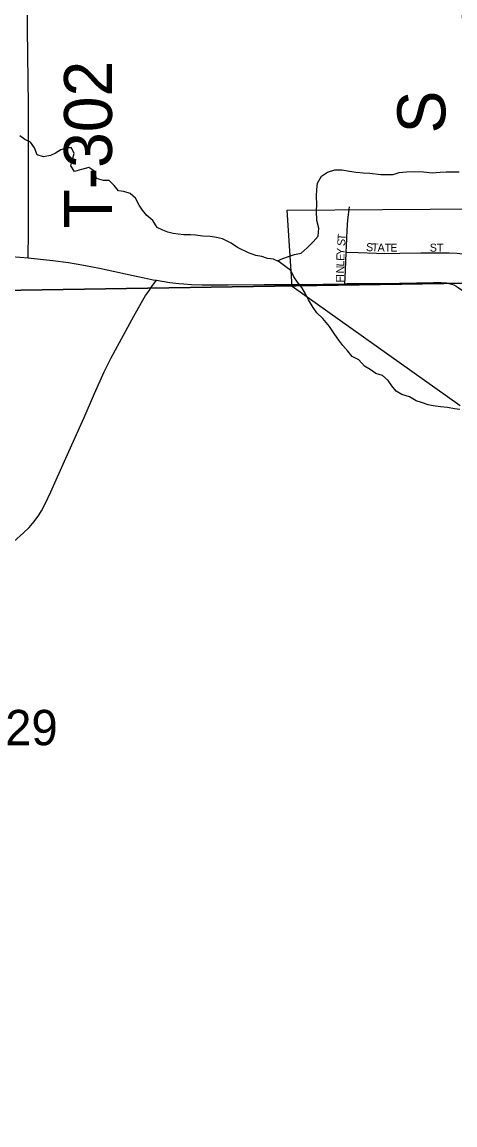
# Model space of a CAD drawing. Extents: x 1985906 to 2360102, y 891258 to 1222054.
# Drawn here: x 2147577 to 2150284, y 999101 to 1005993 of the extents above; entities that cross this region are included whole.
import ezdxf

# ---------------------------------------------------------------- set-up
doc = ezdxf.new("R2010")
doc.units = 0
for name, color, linetype in [('GM_X_City_Street', 7, 'Continuous'), ('GM_X_City_Street_Text', 7, 'Continuous'), ('GM_X_Corporation', 7, 'Continuous'), ('GM_X_County_Road_Text', 7, 'Continuous'), ('GM_X_Minor_River', 7, 'Continuous'), ('GM_X_Section', 7, 'Continuous'), ('GM_X_Section_Text', 7, 'Continuous'), ('GM_X_Township_Road', 7, 'Continuous'), ('GM_X_Township_Road_Text', 7, 'Continuous'), ('GM_X_US_Route', 7, 'Continuous')]:
    doc.layers.add(name, color=color, linetype=linetype)

msp = doc.modelspace()

# ---------------------------------------------------------------- linework, layer by layer
at = {"layer": 'GM_X_City_Street'}
for points in [[(2149604.5, 1004554.5), (2149606.6, 1004593.2), (2149609.8, 1004691.6), (2149614.7, 1004756.6), (2149623, 1004821.8), (2149624.4, 1004838.1)], [(2149594.7, 1004358), (2149596.5, 1004396.7), (2149601.3, 1004494.9), (2149604.5, 1004554.5)], [(2149604.5, 1004554.5), (2149608.6, 1004554.4), (2149679.7, 1004553.3), (2149793.5, 1004548.1), (2149842.2, 1004546.9), (2149939.6, 1004548.5), (2150069.7, 1004550.9), (2150248.8, 1004550.7), (2150297.5, 1004548.5), (2150313.7, 1004546.8), (2150345.6, 1004543.5)]]:
    msp.add_lwpolyline(points, dxfattribs=at)
at = {"layer": 'GM_X_Corporation'}
msp.add_lwpolyline([(2150317.2, 1003594.5), (2149265.4, 1004339.5), (2149235.5, 1004817.2), (2150726.1, 1004827.3)], dxfattribs=at)
at = {"layer": 'GM_X_Minor_River'}
for points in [[(2148086.7, 1005002.3), (2148042.5, 1005016), (2148032.1, 1005058.1), (2147993.7, 1005083.9), (2147947.6, 1005071.5), (2147905.6, 1005059.1), (2147881.2, 1005095), (2147890.9, 1005127.2), (2147902.6, 1005171.5), (2147886.2, 1005207.5), (2147854.1, 1005207.2), (2147820.1, 1005194.9), (2147786.1, 1005174.5), (2147754.2, 1005158.2), (2147710.1, 1005149.8), (2147671.8, 1005163.6), (2147655.4, 1005207.6), (2147629, 1005241.5), (2147594.7, 1005259.3), (2147562.4, 1005281.1)], [(2149174.3, 1004500), (2149207.1, 1004515.6), (2149243.1, 1004527.9), (2149281.2, 1004540.3), (2149323.2, 1004548.7), (2149359.1, 1004581.1), (2149396.9, 1004619.5), (2149428.7, 1004655.9), (2149432.3, 1004704.2), (2149419.9, 1004752.2), (2149417.4, 1004812.4), (2149421, 1004852.6), (2149418.6, 1004904.8), (2149420.2, 1004947), (2149423.9, 1004985.2), (2149449.6, 1005029.5), (2149487.6, 1005055.9), (2149533.6, 1005070.4), (2149575.8, 1005068.7), (2149624, 1005061.1), (2149666.3, 1005055.4), (2149710.5, 1005049.8), (2149752.6, 1005048.1), (2149821, 1005040.6), (2149897.2, 1005041.2), (2149935.3, 1005053.6), (2149981.4, 1005058), (2150029.6, 1005058.4), (2150087.8, 1005056.8), (2150142.1, 1005051.3), (2150192.2, 1005055.7), (2150228.3, 1005058), (2150266.5, 1005056.3), (2150310.7, 1005056.7)], [(2150315.3, 1003571), (2150281.1, 1003576.7), (2150236.8, 1003584.4), (2150192.6, 1003588), (2150148.4, 1003595.7), (2150116.2, 1003601.5), (2150074, 1003615.2), (2150041.8, 1003626.9), (2149999.4, 1003650.7), (2149951.1, 1003666.4), (2149916.8, 1003686.2), (2149888.4, 1003720.1), (2149866, 1003754), (2149831.6, 1003783.8), (2149789.4, 1003797.5), (2149753, 1003821.3), (2149718.7, 1003843.2), (2149682.2, 1003883), (2149641.9, 1003902.8), (2149613.5, 1003936.7), (2149583.1, 1003972.5), (2149558.7, 1004004.5), (2149532.3, 1004040.4), (2149499.8, 1004090.3), (2149457.2, 1004140.2), (2149420.8, 1004176), (2149396.4, 1004209.9), (2149367.9, 1004257.9), (2149349.5, 1004293.9), (2149327.1, 1004333.8), (2149298.7, 1004367.8), (2149276.3, 1004401.7), (2149257.9, 1004439.7), (2149225.6, 1004463.5), (2149185.2, 1004495.3), (2149148.9, 1004511.1), (2149110.7, 1004514.8), (2149076.5, 1004528.6), (2149038.3, 1004534.3), (2148992, 1004550), (2148923.4, 1004583.5), (2148885.1, 1004611.3), (2148830.6, 1004639), (2148792.4, 1004646.7), (2148752.2, 1004652.4), (2148706, 1004656), (2148661.8, 1004661.7), (2148629.7, 1004663.4), (2148587.5, 1004663.1), (2148553.3, 1004666.8), (2148521.2, 1004672.6), (2148489, 1004680.4), (2148456.8, 1004692.2), (2148422.5, 1004709.9), (2148394, 1004753.9), (2148357.6, 1004783.7), (2148329.2, 1004817.6), (2148308.9, 1004849.5), (2148286.4, 1004891.5), (2148252.1, 1004921.4), (2148213.8, 1004933.1), (2148179.6, 1004938.8), (2148153.3, 1004970.8), (2148120.9, 1005002.6), (2148086.7, 1005002.3)]]:
    msp.add_lwpolyline(points, dxfattribs=at)
at = {"layer": 'GM_X_Section'}
for points in [[(2144878.5, 1009582.1), (2147728.3, 1009573.8), (2150295.3, 1009657.4), (2150345.7, 1004360.6), (2144923, 1004275.3)], [(2144923, 1004275.3), (2150345.7, 1004360.6), (2150383.8, 999036.3), (2144919.1, 998954.5)]]:
    msp.add_lwpolyline(points, close=True, dxfattribs=at)
at = {"layer": 'GM_X_Township_Road'}
for points in [[(2147615.5, 1004518.9), (2147615.8, 1004545.9), (2147616.8, 1004654.9), (2147617, 1004966.6), (2147617.4, 1005229.1), (2147616.8, 1005475.1), (2147612, 1005786.7), (2147610.9, 1005950.6), (2147611.8, 1006132.3), (2147610.9, 1006227.8), (2147607.8, 1006541), (2147604.3, 1007164.2), (2147601.2, 1007639.9), (2147596.9, 1007820.3), (2147592.4, 1008115.4), (2147590.8, 1008295.7), (2147587.5, 1008525.3), (2147582.1, 1008754.7), (2147581.6, 1008853), (2147580.5, 1008928.2), (2147578.7, 1009053.2), (2147577.5, 1009132.2), (2147576.7, 1009196.8), (2147575.1, 1009311.5)], [(2147525.4, 1002746.2), (2147586.6, 1002800.7), (2147621.3, 1002835.1), (2147653.1, 1002872.2), (2147681.8, 1002911.7), (2147699, 1002939.3), (2147722, 1002982.5), (2147756.9, 1003056.6), (2147849.7, 1003266.9), (2147964.3, 1003521.4), (2148029.3, 1003672.2), (2148090.7, 1003806.7), (2148133.9, 1003895.4), (2148172.9, 1003967.8), (2148275.3, 1004155.1), (2148323.5, 1004241.4), (2148349.7, 1004283.4), (2148368.9, 1004311), (2148389.2, 1004340.1), (2148417.5, 1004379.7)]]:
    msp.add_lwpolyline(points, dxfattribs=at)
at = {"layer": 'GM_X_US_Route'}
for points in [[(2147458.3, 1004533), (2147615.5, 1004518.9), (2147632.9, 1004517.4), (2147768.9, 1004503.2), (2147867.8, 1004490.6), (2147915.5, 1004483), (2147973.6, 1004472.6), (2148060.8, 1004454.9), (2148272.2, 1004408.2), (2148340, 1004393.9), (2148397.4, 1004382.9), (2148417.5, 1004379.7), (2148501.1, 1004366.4), (2148519.4, 1004364.1), (2148557, 1004360.1), (2148589.2, 1004356.7), (2148636.5, 1004353.8), (2148702.1, 1004350.9), (2148865.9, 1004350.9), (2149090.9, 1004352.7), (2149227.3, 1004353.8), (2149355.6, 1004353.1)], [(2149355.6, 1004353.1), (2149460.8, 1004355.6), (2149594.7, 1004358), (2149610, 1004358.2), (2149757.1, 1004359.6), (2149937.2, 1004360.7), (2150150.1, 1004366.1), (2150198.8, 1004365.4), (2150231, 1004362.6), (2150246.7, 1004359.7), (2150262, 1004355.5), (2150276.9, 1004349.9), (2150291.2, 1004342.8), (2150305, 1004334.6), (2150330.9, 1004315.5), (2150343.7, 1004304.4)]]:
    msp.add_lwpolyline(points, dxfattribs=at)

# ---------------------------------------------------------------- texts
at = {"layer": 'GM_X_City_Street_Text'}
for s, rotation, p in [('T', 85.59709, (2149599.1, 1004627.4)), ('Y', 86.89472, (2149593.1, 1004535.5)), ('S', 85.62434, (2149596.5, 1004592.3)), ('S', 356.28223, (2149726.7, 1004562.7)), ('T', 357.289, (2149762.8, 1004560.4)), ('A', 359.57615, (2149800.1, 1004558.7)), ('T', 0.01484, (2149844.6, 1004558.3)), ('E', 0.00001, (2149879.8, 1004558.3)), ('ST', 0.00001, (2150126.5, 1004558.3)), ('E', 88.663, (2149592.3, 1004500.8)), ('N', 88.64465, (2149590.4, 1004421.6)), ('L', 88.63379, (2149591.4, 1004465.5)), ('F', 88.63379, (2149589, 1004364.4)), ('I', 88.65428, (2149589.9, 1004399.6))]:
    msp.add_text(s, height=50, rotation=rotation, dxfattribs=at).set_placement(p)
at = {"layer": 'GM_X_County_Road_Text'}
msp.add_text('S', height=300, rotation=90, dxfattribs=at).set_placement((2150224, 1005296.9))
at = {"layer": 'GM_X_Section_Text'}
msp.add_text('29', height=221, rotation=0.00001, dxfattribs=at).set_placement((2147471.1, 1001473.7))
at = {"layer": 'GM_X_Township_Road_Text'}
msp.add_text('T-302', height=300, rotation=90, dxfattribs=at).set_placement((2148139.2, 1004702.9))

doc.saveas('drawing.dxf')
